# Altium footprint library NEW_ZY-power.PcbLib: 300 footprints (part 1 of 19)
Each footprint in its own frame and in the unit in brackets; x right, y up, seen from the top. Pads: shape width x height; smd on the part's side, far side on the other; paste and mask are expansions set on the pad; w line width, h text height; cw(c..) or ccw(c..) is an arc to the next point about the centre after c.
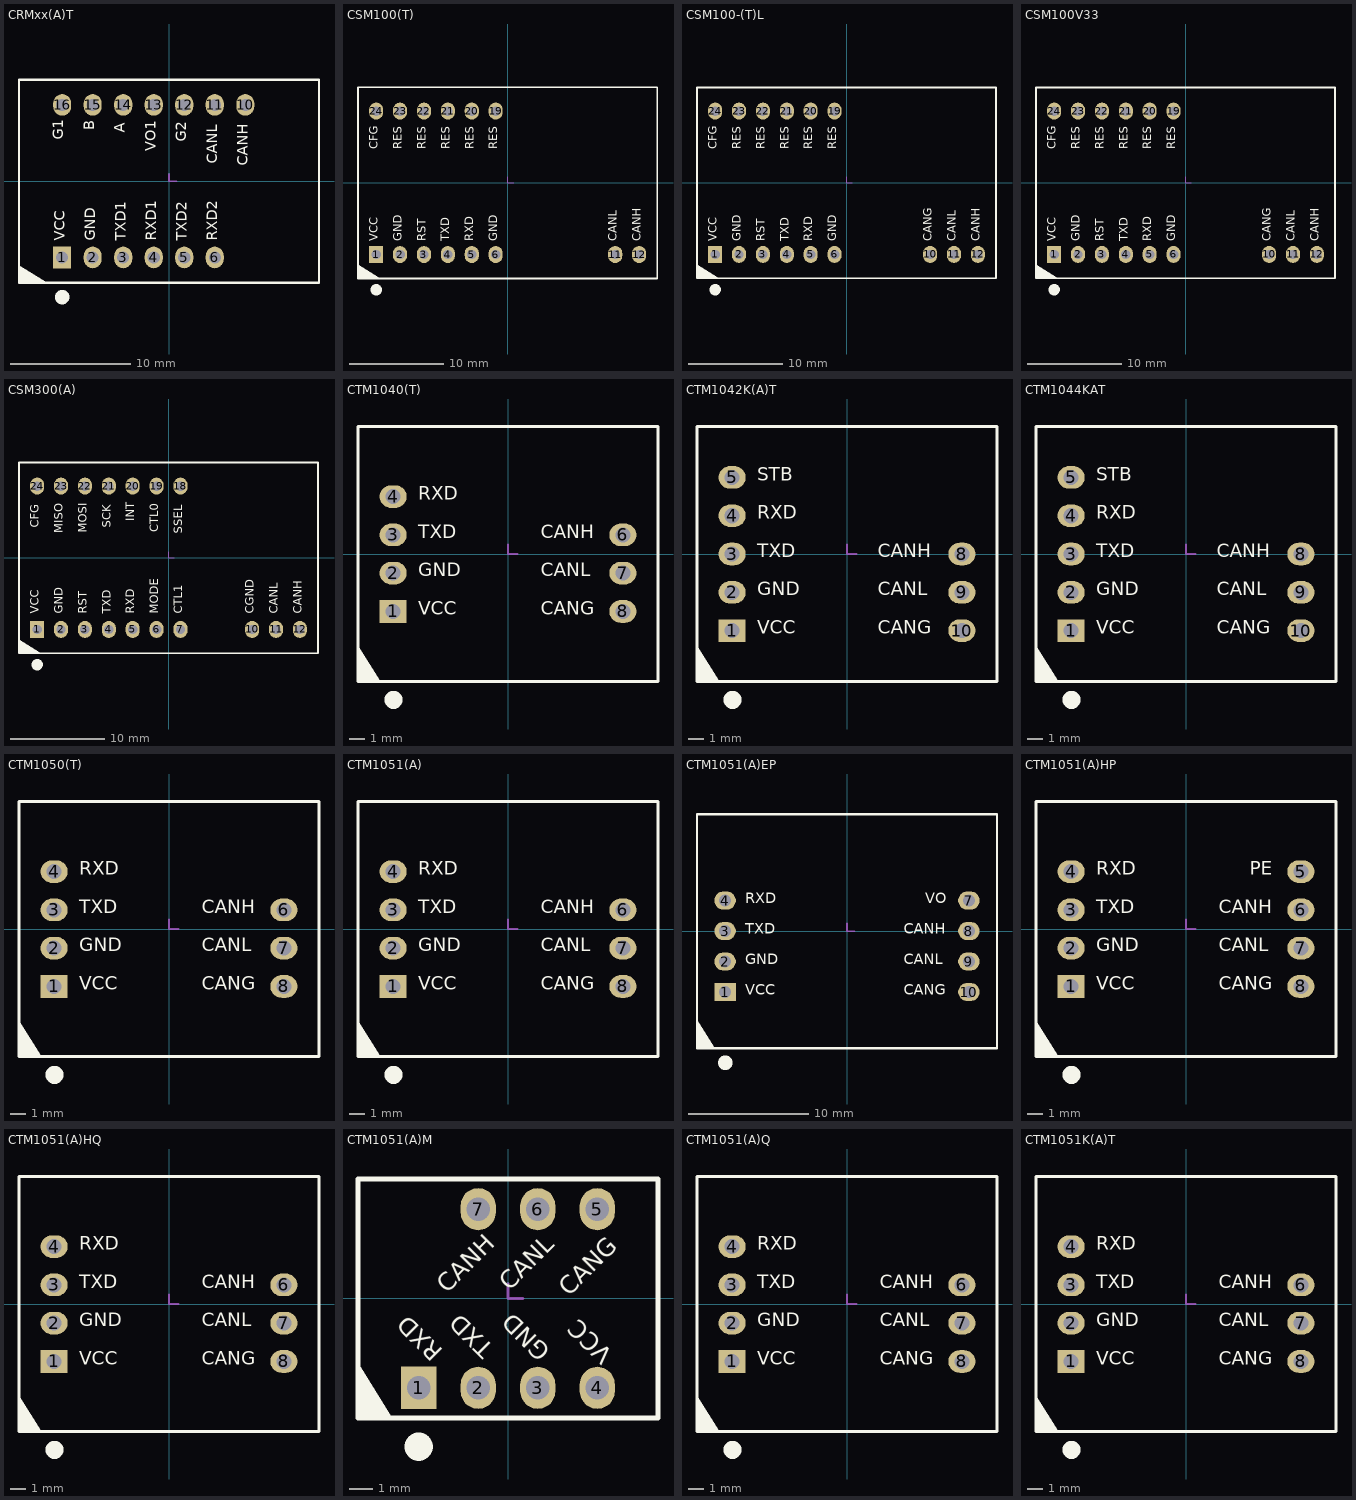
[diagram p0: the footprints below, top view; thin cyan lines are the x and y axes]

## CRMxx(A)T [mm]
height 7.1
pads (13):
  rect 1.5x1.8 hole 1: 1(-8.89,-6.35)
  oval 1.5x1.8 hole 1: 2(-6.35,-6.35) 3(-3.81,-6.35) 4(-1.27,-6.35) 5(1.27,-6.35) 6(3.81,-6.35) 10(6.35,6.35) 11(3.81,6.35) 12(1.27,6.35) 13(-1.27,6.35) 14(-3.81,6.35) 15(-6.35,6.35) 16(-8.89,6.35)
Top Overlay:
  circle w1: c-8.89,-9.649 r0.1
  region: -10.263,-8.45 -12.49,-8.45 -12.49,-6.99 -10.338,-8.338
  lines w0.2: -12.49,-8.45 12.49,-8.45 12.49,8.45 -12.49,8.45 -12.49,-8.45
  text "G1" at -8.509,3.469 h1.52
  text "B" at -5.948,4.227 h1.52
  text "A" at -3.387,4.053 h1.52
  text "VO1" at -0.826,2.493 h1.52
  text "G2" at 1.736,3.29 h1.52
  text "CANL" at 4.297,1.446 h1.52
  text "RXD2" at 4.318,-4.954 h1.52
  text "TXD2" at 1.778,-4.954 h1.52
  text "RXD1" at -0.762,-4.954 h1.52
  text "TXD1" at -3.302,-4.954 h1.52
  text "GND" at -5.842,-4.954 h1.52
  text "CANH" at 6.858,1.282 h1.52
  text "VCC" at -8.382,-4.953 h1.52
Mechanical 15:
  lines w0.127: 0,0.635 0,0 0.635,0

## CSM100(T) [mm] "嵌入式CAN-bus接口芯片"
height 9.4
pads (14):
  rect 1.5x1.8 hole 1: 1(-13.97,-7.62)
  oval 1.5x1.8 hole 1: 2(-11.43,-7.62) 3(-8.89,-7.62) 4(-6.35,-7.62) 5(-3.81,-7.62) 6(-1.27,-7.62) 11(11.43,-7.62) 12(13.97,-7.62) 19(-1.27,7.62) 20(-3.81,7.62) 21(-6.35,7.62) 22(-8.89,7.62) 23(-11.43,7.62) 24(-13.97,7.62)
Top Overlay:
  circle w1: c-13.97,-11.368 r0.1
  region: -13.673,-10.15 -15.9,-10.15 -15.9,-8.69 -13.748,-10.038
  lines w0.2: -15.9,-10.15 -15.9,10.15 15.9,10.15 15.9,-10.15 -15.9,-10.15
  text "CFG" at -13.462,3.556 h1.52
  text "RES" at -8.382,3.556 h1.52
  text "RES" at -5.842,3.556 h1.52
  text "RES" at -3.302,3.556 h1.52
  text "RES" at -0.762,3.556 h1.52
  text "RES" at -10.922,3.556 h1.52
  text "GND" at -0.787,-6.224 h1.52
  text "CANH" at 14.453,-6.224 h1.52
  text "CANL" at 11.913,-6.224 h1.52
  text "RXD" at -3.327,-6.224 h1.52
  text "TXD" at -5.867,-6.224 h1.52
  text "RST" at -8.407,-6.224 h1.52
  text "GND" at -10.947,-6.224 h1.52
  text "VCC" at -13.487,-6.223 h1.52
Mechanical 15:
  lines w0.127: 0,0.635 0,0 0.635,0

## CSM100-(T)L [mm]
pads (15):
  rect 1.5x1.8 hole 1: 1(-13.97,-7.62)
  oval 1.5x1.8 hole 1: 2(-11.43,-7.62) 3(-8.89,-7.62) 4(-6.35,-7.62) 5(-3.81,-7.62) 6(-1.27,-7.62) 10(8.89,-7.62) 11(11.43,-7.62) 12(13.97,-7.62) 19(-1.27,7.62) 20(-3.81,7.62) 21(-6.35,7.62) 22(-8.89,7.62) 23(-11.43,7.62) 24(-13.97,7.62)
Top Overlay:
  circle w1: c-13.97,-11.368 r0.1
  region: -15.9,-10.15 -15.9,-8.69 -13.748,-10.038 -13.589,-10.15
  lines w0.2: -15.9,-10.15 -15.9,10.15 15.9,10.15 15.9,-10.15 -15.9,-10.15
  text "CANG" at 9.398,-6.223 h1.52
  text "CFG" at -13.462,3.556 h1.52
  text "RES" at -8.382,3.556 h1.52
  text "RES" at -5.842,3.556 h1.52
  text "RES" at -3.302,3.556 h1.52
  text "GND" at -0.762,-6.223 h1.52
  text "RES" at -0.762,3.556 h1.52
  text "CANH" at 14.478,-6.223 h1.52
  text "CANL" at 11.938,-6.223 h1.52
  text "RXD" at -3.302,-6.223 h1.52
  text "TXD" at -5.842,-6.223 h1.52
  text "RST" at -8.382,-6.223 h1.52
  text "GND" at -10.922,-6.223 h1.52
  text "VCC" at -13.462,-6.223 h1.52
  text "RES" at -10.922,3.556 h1.52
Mechanical 15:
  lines w0.127: 0,0.635 0,0 0.635,0

## CSM100V33 [mm]
pads (15):
  rect 1.5x1.8 hole 1: 1(-13.97,-7.62)
  oval 1.5x1.8 hole 1: 2(-11.43,-7.62) 3(-8.89,-7.62) 4(-6.35,-7.62) 5(-3.81,-7.62) 6(-1.27,-7.62) 10(8.89,-7.62) 11(11.43,-7.62) 12(13.97,-7.62) 19(-1.27,7.62) 20(-3.81,7.62) 21(-6.35,7.62) 22(-8.89,7.62) 23(-11.43,7.62) 24(-13.97,7.62)
Top Overlay:
  circle w1: c-13.97,-11.368 r0.1
  region: -13.673,-10.15 -15.9,-10.15 -15.9,-8.69 -13.748,-10.038
  lines w0.2: -15.9,-10.15 15.9,-10.15 15.9,10.15 -15.9,10.15 -15.9,-10.15
  text "GND" at -10.922,-6.224 h1.52
  text "TXD" at -5.842,-6.224 h1.52
  text "RXD" at -3.302,-6.224 h1.52
  text "CANL" at 11.938,-6.224 h1.52
  text "CANH" at 14.478,-6.224 h1.52
  text "GND" at -0.762,-6.224 h1.52
  text "CANG" at 9.398,-6.224 h1.52
  text "CFG" at -13.462,3.556 h1.52
  text "RES" at -8.382,3.556 h1.52
  text "RES" at -5.842,3.556 h1.52
  text "RES" at -3.302,3.556 h1.52
  text "RES" at -0.762,3.556 h1.52
  text "RST" at -8.382,-6.224 h1.52
  text "VCC" at -13.462,-6.223 h1.52
  text "RES" at -10.922,3.556 h1.52
Mechanical 15:
  lines w0.127: 0,0.635 0,0 0.635,0

## CSM300(A) [mm]
height 6.5
pads (17):
  rect 1.5x1.8 hole 1: 1(-13.97,-7.62)
  oval 1.5x1.8 hole 1: 2(-11.43,-7.62) 3(-8.89,-7.62) 4(-6.35,-7.62) 5(-3.81,-7.62) 6(-1.27,-7.62) 7(1.27,-7.62) 10(8.89,-7.62) 11(11.43,-7.62) 12(13.97,-7.62) 18(1.27,7.62) 19(-1.27,7.62) 20(-3.81,7.62) 21(-6.35,7.62) 22(-8.89,7.62) 23(-11.43,7.62) 24(-13.97,7.62)
Top Overlay:
  circle w1: c-13.97,-11.368 r0.1
  region: -13.673,-10.15 -15.9,-10.15 -15.9,-8.69 -13.748,-10.038
  lines w0.2: -15.9,-10.15 15.9,-10.15 15.9,10.15 -15.9,10.15 -15.9,-10.15
  text "SSEL" at 1.778,2.54 h1.52
  text "CTL0" at -0.762,2.717 h1.52
  text "INT" at -3.302,3.876 h1.52
  text "SCK" at -5.842,3.177 h1.52
  text "MOSI" at -8.382,2.654 h1.52
  text "MISO" at -10.922,2.593 h1.52
  text "CFG" at -13.462,3.192 h1.52
  text "CANH" at 14.478,-5.969 h1.52
  text "CANL" at 11.938,-5.969 h1.52
  text "CGND" at 9.398,-5.969 h1.52
  text "CTL1" at 1.778,-5.969 h1.52
  text "MODE" at -0.762,-5.969 h1.52
  text "RXD" at -3.302,-5.969 h1.52
  text "TXD" at -5.842,-5.969 h1.52
  text "RST" at -8.382,-5.969 h1.52
  text "GND" at -10.922,-5.969 h1.52
  text "VCC" at -13.462,-5.969 h1.52
Mechanical 15:
  lines w0.127: 0,0.635 0,0 0.635,0

## CTM1040(T) [mm]
height 7.1
pads (7):
  rect 1.8x1.5 hole 1: 1(-7.62,-3.81)
  oval 1.8x1.5 hole 1: 2(-7.62,-1.27) 3(-7.62,1.27) 4(-7.62,3.81) 6(7.62,1.27) 7(7.62,-1.27) 8(7.62,-3.81)
Top Overlay:
  circle w1: c-7.593,-9.675 r0.1
  region: -9.95,-6.12 -9.95,-8.45 -8.49,-8.45
  lines w0.2: -9.95,-8.45 9.95,-8.45 9.95,8.45 -9.95,8.45 -9.95,-8.45
  text "CANG" at 2.189,-4.318 h1.52
  text "CANL" at 2.189,-1.778 h1.52
  text "CANH" at 2.189,0.762 h1.52
  text "GND" at -5.939,-1.778 h1.52
  text "TXD" at -5.939,0.762 h1.52
  text "RXD" at -5.969,3.302 h1.52
  text "VCC" at -5.938,-4.318 h1.52
Mechanical 15:
  lines w0.127: 0,0.635 0,0 0.635,0

## CTM1042K(A)T [mm]
height 7.1
pads (8):
  rect 1.8x1.5 hole 1: 1(-7.62,-5.08)
  oval 1.8x1.5 hole 1: 2(-7.62,-2.54) 3(-7.62,0) 4(-7.62,2.54) 5(-7.62,5.08) 8(7.62,0) 9(7.62,-2.54) 10(7.62,-5.08)
Top Overlay:
  circle w1: c-7.593,-9.675 r0.1
  region: -9.95,-6.12 -9.95,-8.45 -8.49,-8.45
  lines w0.2: -9.95,-8.45 -9.95,8.45 9.95,8.45 9.95,-8.45 -9.95,-8.45
  text "CANG" at 2.032,-5.588 h1.52
  text "CANL" at 2.032,-3.048 h1.52
  text "CANH" at 2.032,-0.508 h1.52
  text "STB" at -5.939,4.572 h1.52
  text "RXD" at -5.939,2.032 h1.52
  text "TXD" at -5.939,-0.508 h1.52
  text "VCC" at -5.938,-5.588 h1.52
  text "GND" at -5.939,-3.048 h1.52
Mechanical 15:
  lines w0.127: 0,0.635 0,0 0.635,0

## CTM1044KAT [mm]
height 7.1
pads (8):
  rect 1.8x1.5 hole 1: 1(-7.62,-5.08)
  oval 1.8x1.5 hole 1: 2(-7.62,-2.54) 3(-7.62,0) 4(-7.62,2.54) 5(-7.62,5.08) 8(7.62,0) 9(7.62,-2.54) 10(7.62,-5.08)
Top Overlay:
  circle w1: c-7.593,-9.675 r0.1
  region: -9.95,-6.12 -9.95,-8.45 -8.49,-8.45
  lines w0.2: -9.95,-8.45 9.95,-8.45 9.95,8.45 -9.95,8.45 -9.95,-8.45
  text "GND" at -5.939,-3.048 h1.52
  text "VCC" at -5.938,-5.588 h1.52
  text "TXD" at -5.939,-0.508 h1.52
  text "RXD" at -5.939,2.032 h1.52
  text "STB" at -5.939,4.572 h1.52
  text "CANH" at 2.032,-0.508 h1.52
  text "CANL" at 2.032,-3.048 h1.52
  text "CANG" at 2.032,-5.588 h1.52
Mechanical 15:
  lines w0.127: 0,0.635 0,0 0.635,0

## CTM1050(T) [mm]
height 7.1
pads (7):
  rect 1.8x1.5 hole 1: 1(-7.62,-3.81)
  oval 1.8x1.5 hole 1: 2(-7.62,-1.27) 3(-7.62,1.27) 4(-7.62,3.81) 6(7.62,1.27) 7(7.62,-1.27) 8(7.62,-3.81)
Top Overlay:
  circle w1: c-7.593,-9.675 r0.1
  region: -9.95,-6.12 -9.95,-8.45 -8.49,-8.45
  lines w0.2: -9.95,-8.45 9.95,-8.45 9.95,8.45 -9.95,8.45 -9.95,-8.45
  text "CANG" at 2.189,-4.318 h1.52
  text "CANL" at 2.189,-1.778 h1.52
  text "CANH" at 2.189,0.762 h1.52
  text "GND" at -5.939,-1.778 h1.52
  text "TXD" at -5.939,0.762 h1.52
  text "RXD" at -5.969,3.302 h1.52
  text "VCC" at -5.938,-4.318 h1.52
Mechanical 15:
  lines w0.127: 0,0.635 0,0 0.635,0

## CTM1051(A) [mm]
height 7.1
pads (7):
  rect 1.8x1.5 hole 1: 1(-7.62,-3.81)
  oval 1.8x1.5 hole 1: 2(-7.62,-1.27) 3(-7.62,1.27) 4(-7.62,3.81) 6(7.62,1.27) 7(7.62,-1.27) 8(7.62,-3.81)
Top Overlay:
  circle w1: c-7.593,-9.675 r0.1
  region: -9.95,-6.12 -9.95,-8.45 -8.49,-8.45
  lines w0.2: -9.95,-8.45 9.95,-8.45 9.95,8.45 -9.95,8.45 -9.95,-8.45
  text "CANG" at 2.189,-4.318 h1.52
  text "CANL" at 2.189,-1.778 h1.52
  text "CANH" at 2.189,0.762 h1.52
  text "GND" at -5.939,-1.778 h1.52
  text "TXD" at -5.939,0.762 h1.52
  text "RXD" at -5.969,3.302 h1.52
  text "VCC" at -5.938,-4.318 h1.52
Mechanical 15:
  lines w0.127: 0,0.635 0,0 0.635,0

## CTM1051(A)EP [mm]
height 9.1
pads (8):
  rect 1.8x1.5 hole 1: 1(-10.16,-5.08)
  oval 1.8x1.5 hole 1: 2(-10.16,-2.54) 3(-10.16,0) 4(-10.16,2.54) 7(10.16,2.54) 8(10.16,0) 9(10.16,-2.54) 10(10.16,-5.08)
Top Overlay:
  circle w1: c-10.143,-10.975 r0.1
  region: -12.5,-7.42 -12.5,-9.75 -11.04,-9.75
  lines w0.2: -12.5,-9.75 12.5,-9.75 12.5,9.75 -12.5,9.75 -12.5,-9.75
  text "VO" at 6.509,2.032 h1.52
  text "CANG" at 4.729,-5.588 h1.52
  text "CANL" at 4.729,-3.048 h1.52
  text "CANH" at 4.729,-0.508 h1.52
  text "GND" at -8.479,-3.048 h1.52
  text "TXD" at -8.479,-0.508 h1.52
  text "RXD" at -8.479,2.032 h1.52
  text "VCC" at -8.478,-5.588 h1.52
Mechanical 15:
  lines w0.127: 0,0.635 0,0 0.635,0

## CTM1051(A)HP [mm]
height 7.1
pads (8):
  rect 1.8x1.5 hole 1: 1(-7.62,-3.81)
  oval 1.8x1.5 hole 1: 2(-7.62,-1.27) 3(-7.62,1.27) 4(-7.62,3.81) 5(7.62,3.81) 6(7.62,1.27) 7(7.62,-1.27) 8(7.62,-3.81)
Top Overlay:
  circle w1: c-7.593,-9.675 r0.1
  region: -9.95,-6.12 -9.95,-8.45 -8.49,-8.45
  lines w0.2: -9.95,-8.45 -9.95,8.45 9.95,8.45 9.95,-8.45 -9.95,-8.45
  text "VCC" at -5.938,-4.318 h1.52
  text "RXD" at -5.969,3.302 h1.52
  text "TXD" at -5.939,0.762 h1.52
  text "GND" at -5.939,-1.778 h1.52
  text "CANH" at 2.189,0.762 h1.52
  text "CANL" at 2.189,-1.778 h1.52
  text "CANG" at 2.189,-4.318 h1.52
  text "PE" at 4.23,3.302 h1.52
Mechanical 15:
  lines w0.127: 0,0.635 0,0 0.635,0

## CTM1051(A)HQ [mm]
height 7.1
pads (7):
  rect 1.8x1.5 hole 1: 1(-7.62,-3.81)
  oval 1.8x1.5 hole 1: 2(-7.62,-1.27) 3(-7.62,1.27) 4(-7.62,3.81) 6(7.62,1.27) 7(7.62,-1.27) 8(7.62,-3.81)
Top Overlay:
  circle w1: c-7.593,-9.675 r0.1
  region: -9.95,-6.12 -9.95,-8.45 -8.49,-8.45
  lines w0.2: -9.95,-8.45 9.95,-8.45 9.95,8.45 -9.95,8.45 -9.95,-8.45
  text "CANG" at 2.189,-4.318 h1.52
  text "CANL" at 2.189,-1.778 h1.52
  text "CANH" at 2.189,0.762 h1.52
  text "GND" at -5.939,-1.778 h1.52
  text "TXD" at -5.939,0.762 h1.52
  text "RXD" at -5.939,3.302 h1.52
  text "VCC" at -5.938,-4.318 h1.52
Mechanical 15:
  lines w0.127: 0,0.635 0,0 0.635,0

## CTM1051(A)M [mm]
height 7.7
pads (7):
  rect 1.5x1.8 hole 1: 1(-3.81,-3.81)
  oval 1.5x1.8 hole 1: 2(-1.27,-3.81) 3(1.27,-3.81) 4(3.81,-3.81) 5(3.81,3.81) 6(1.27,3.81) 7(-1.27,3.81)
Top Overlay:
  circle w1: c-3.81,-6.323 r0.1
  region: -6.4,-2.77 -6.4,-5.1 -4.94,-5.1
  lines w0.2: -6.4,-5.1 -6.4,5.1 6.4,5.1 6.4,-5.1 -6.4,-5.1
  text "CANG" at 2.794,-0.127 h1.27
  text "CANL" at 0.254,0.127 h1.27
  text "CANH" at -2.413,0 h1.27
  text "RXD" at -2.54,-2.032 h1.27
  text "TXD" at -0.381,-1.905 h1.27
  text "GND" at 2.032,-2.032 h1.27
  text "VCC" at 4.699,-2.159 h1.27
Mechanical 15:
  lines w0.127: 0,0.635 0,0 0.635,0

## CTM1051(A)Q [mm]
height 7.1
pads (7):
  rect 1.8x1.5 hole 1: 1(-7.62,-3.81)
  oval 1.8x1.5 hole 1: 2(-7.62,-1.27) 3(-7.62,1.27) 4(-7.62,3.81) 6(7.62,1.27) 7(7.62,-1.27) 8(7.62,-3.81)
Top Overlay:
  circle w1: c-7.593,-9.673 r0.1
  region: -9.95,-6.12 -9.95,-8.45 -8.49,-8.45
  lines w0.2: -9.95,-8.45 9.95,-8.45 9.95,8.45 -9.95,8.45 -9.95,-8.45
  text "CANG" at 2.189,-4.318 h1.52
  text "CANL" at 2.189,-1.778 h1.52
  text "CANH" at 2.189,0.762 h1.52
  text "GND" at -5.939,-1.778 h1.52
  text "TXD" at -5.939,0.762 h1.52
  text "RXD" at -5.939,3.302 h1.52
  text "VCC" at -5.938,-4.318 h1.52
Mechanical 15:
  lines w0.127: 0,0.635 0,0 0.635,0

## CTM1051K(A)T [mm]
height 7.1
pads (7):
  rect 1.8x1.5 hole 1: 1(-7.62,-3.81)
  oval 1.8x1.5 hole 1: 2(-7.62,-1.27) 3(-7.62,1.27) 4(-7.62,3.81) 6(7.62,1.27) 7(7.62,-1.27) 8(7.62,-3.81)
Top Overlay:
  circle w1: c-7.593,-9.675 r0.1
  region: -9.95,-6.12 -9.95,-8.45 -8.49,-8.45
  lines w0.2: -9.95,-8.45 -9.95,8.45 9.95,8.45 9.95,-8.45 -9.95,-8.45
  text "VCC" at -5.938,-4.318 h1.52
  text "RXD" at -5.939,3.302 h1.52
  text "TXD" at -5.939,0.762 h1.52
  text "GND" at -5.939,-1.778 h1.52
  text "CANH" at 2.189,0.762 h1.52
  text "CANL" at 2.189,-1.778 h1.52
  text "CANG" at 2.189,-4.318 h1.52
Mechanical 15:
  lines w0.127: 0,0.635 0,0 0.635,0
